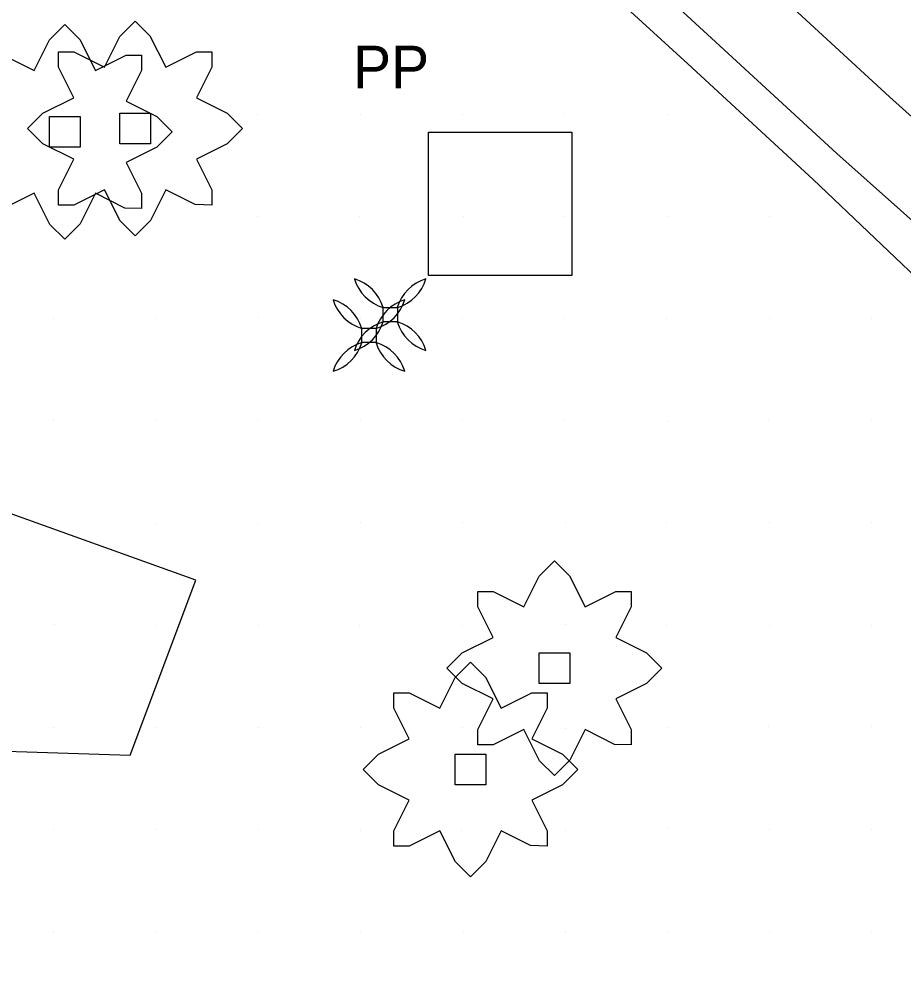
# Model space of a CAD drawing. Extents: x 1602514 to 1609837, y 863887 to 871157.
# Drawn here: x 1605113.6 to 1605243.4, y 866343.2 to 866482.9 of the extents above; entities that cross this region are included whole.
import ezdxf

# ---------------------------------------------------------------- set-up
doc = ezdxf.new("R2010")
doc.units = 0
for name, color, linetype in [('Environmental-New trees', 7, 'Continuous'), ('Photo-Anchor', 7, 'Continuous'), ('Survey-Centerline', 7, 'Continuous'), ('Survey-Edge of pavement', 7, 'Continuous'), ('Survey-Shoulders', 7, 'Continuous'), ('Survey-Spot dirt', 7, 'Continuous'), ('Survey-Vegetation trees', 7, 'Continuous'), ('Utility-Pole', 7, 'Continuous')]:
    doc.layers.add(name, color=color, linetype=linetype)

msp = doc.modelspace()

# ---------------------------------------------------------------- linework, layer by layer
at = {"layer": 'Environmental-New trees'}
msp.add_lwpolyline([(1605111.28, 866477.59), (1605115.78, 866475.34), (1605118.03, 866479.84), (1605120.28, 866482.1), (1605122.47, 866479.9), (1605124.78, 866475.34), (1605129.28, 866477.59), (1605131.53, 866477.59), (1605131.53, 866475.34), (1605129.28, 866470.84), (1605133.78, 866468.59), (1605136.03, 866466.34), (1605133.78, 866464.09), (1605129.28, 866461.84), (1605131.53, 866457.34), (1605131.53, 866455.09), (1605129.11, 866455.17), (1605124.78, 866457.34), (1605122.53, 866452.84), (1605120.28, 866450.59), (1605118.09, 866452.78), (1605115.78, 866457.34), (1605111.28, 866455.09)], dxfattribs=at)
msp.add_lwpolyline([(1605111.28, 866477.59), (1605115.78, 866475.34), (1605118.03, 866479.84), (1605120.28, 866482.1), (1605122.47, 866479.9), (1605124.78, 866475.34), (1605129.28, 866477.59), (1605131.53, 866477.59), (1605131.53, 866475.34), (1605129.28, 866470.84), (1605133.78, 866468.59), (1605136.03, 866466.34), (1605133.78, 866464.09), (1605129.28, 866461.84), (1605131.53, 866457.34), (1605131.53, 866455.09), (1605129.11, 866455.17), (1605124.78, 866457.34), (1605122.53, 866452.84), (1605120.28, 866450.59), (1605118.09, 866452.78), (1605115.78, 866457.34), (1605111.28, 866455.09)], dxfattribs=at)
for points in [[(1605119.34, 866478.12), (1605121.59, 866478.12), (1605126.09, 866475.87), (1605128.34, 866480.37), (1605130.59, 866482.62), (1605132.78, 866480.43), (1605135.09, 866475.87), (1605139.59, 866478.12), (1605141.84, 866478.12), (1605141.84, 866475.87), (1605139.59, 866471.37), (1605144.09, 866469.12), (1605146.34, 866466.87), (1605144.09, 866464.62), (1605139.59, 866462.37), (1605141.84, 866457.87), (1605141.84, 866455.62), (1605139.41, 866455.7), (1605135.09, 866457.87), (1605132.84, 866453.37), (1605130.59, 866451.12), (1605128.4, 866453.31), (1605126.09, 866457.87), (1605121.59, 866455.62), (1605119.34, 866455.62), (1605119.34, 866457.87), (1605121.59, 866462.37), (1605117.08, 866464.62), (1605114.83, 866466.87), (1605117.08, 866469.12), (1605121.59, 866471.37), (1605119.34, 866475.87)], [(1605119.34, 866478.12), (1605121.59, 866478.12), (1605126.09, 866475.87), (1605128.34, 866480.37), (1605130.59, 866482.62), (1605132.78, 866480.43), (1605135.09, 866475.87), (1605139.59, 866478.12), (1605141.84, 866478.12), (1605141.84, 866475.87), (1605139.59, 866471.37), (1605144.09, 866469.12), (1605146.34, 866466.87), (1605144.09, 866464.62), (1605139.59, 866462.37), (1605141.84, 866457.87), (1605141.84, 866455.62), (1605139.41, 866455.7), (1605135.09, 866457.87), (1605132.84, 866453.37), (1605130.59, 866451.12), (1605128.4, 866453.31), (1605126.09, 866457.87), (1605121.59, 866455.62), (1605119.34, 866455.62), (1605119.34, 866457.87), (1605121.59, 866462.37), (1605117.08, 866464.62), (1605114.83, 866466.87), (1605117.08, 866469.12), (1605121.59, 866471.37), (1605119.34, 866475.87)], [(1605122.53, 866468.59), (1605122.53, 866464.09), (1605118.03, 866464.09), (1605118.03, 866468.59)], [(1605122.53, 866468.59), (1605122.53, 866464.09), (1605118.03, 866464.09), (1605118.03, 866468.59)], [(1605132.84, 866469.12), (1605132.84, 866464.62), (1605128.34, 866464.62), (1605128.34, 866469.12)], [(1605132.84, 866469.12), (1605132.84, 866464.62), (1605128.34, 866464.62), (1605128.34, 866469.12)], [(1605180.84, 866398.9), (1605183.09, 866398.9), (1605187.59, 866396.65), (1605189.84, 866401.15), (1605192.09, 866403.4), (1605194.29, 866401.21), (1605196.59, 866396.65), (1605201.09, 866398.9), (1605203.34, 866398.9), (1605203.34, 866396.65), (1605201.09, 866392.15), (1605205.6, 866389.9), (1605207.85, 866387.65), (1605205.6, 866385.4), (1605201.09, 866383.15), (1605203.34, 866378.65), (1605203.34, 866376.4), (1605200.92, 866376.48), (1605196.59, 866378.65), (1605194.34, 866374.15), (1605192.09, 866371.9), (1605189.9, 866374.09), (1605187.59, 866378.65), (1605183.09, 866376.4), (1605180.84, 866376.4), (1605180.84, 866378.65), (1605183.09, 866383.15), (1605178.59, 866385.4), (1605176.34, 866387.65), (1605178.59, 866389.9), (1605183.09, 866392.15), (1605180.84, 866396.65)], [(1605180.84, 866398.9), (1605183.09, 866398.9), (1605187.59, 866396.65), (1605189.84, 866401.15), (1605192.09, 866403.4), (1605194.29, 866401.21), (1605196.59, 866396.65), (1605201.09, 866398.9), (1605203.34, 866398.9), (1605203.34, 866396.65), (1605201.09, 866392.15), (1605205.6, 866389.9), (1605207.85, 866387.65), (1605205.6, 866385.4), (1605201.09, 866383.15), (1605203.34, 866378.65), (1605203.34, 866376.4), (1605200.92, 866376.48), (1605196.59, 866378.65), (1605194.34, 866374.15), (1605192.09, 866371.9), (1605189.9, 866374.09), (1605187.59, 866378.65), (1605183.09, 866376.4), (1605180.84, 866376.4), (1605180.84, 866378.65), (1605183.09, 866383.15), (1605178.59, 866385.4), (1605176.34, 866387.65), (1605178.59, 866389.9), (1605183.09, 866392.15), (1605180.84, 866396.65)], [(1605194.34, 866389.9), (1605194.34, 866385.4), (1605189.84, 866385.4), (1605189.84, 866389.9)], [(1605194.34, 866389.9), (1605194.34, 866385.4), (1605189.84, 866385.4), (1605189.84, 866389.9)], [(1605168.53, 866384.06), (1605170.78, 866384.06), (1605175.28, 866381.81), (1605177.53, 866386.31), (1605179.78, 866388.56), (1605181.97, 866386.37), (1605184.28, 866381.81), (1605188.78, 866384.06), (1605191.03, 866384.06), (1605191.03, 866381.81), (1605188.78, 866377.31), (1605193.28, 866375.06), (1605195.53, 866372.81), (1605193.28, 866370.56), (1605188.78, 866368.31), (1605191.03, 866363.81), (1605191.03, 866361.56), (1605188.61, 866361.64), (1605184.28, 866363.81), (1605182.03, 866359.31), (1605179.78, 866357.06), (1605177.59, 866359.25), (1605175.28, 866363.81), (1605170.78, 866361.56), (1605168.53, 866361.56), (1605168.53, 866363.81), (1605170.78, 866368.31), (1605166.28, 866370.56), (1605164.03, 866372.81), (1605166.28, 866375.06), (1605170.78, 866377.31), (1605168.53, 866381.81)], [(1605168.53, 866384.06), (1605170.78, 866384.06), (1605175.28, 866381.81), (1605177.53, 866386.31), (1605179.78, 866388.56), (1605181.97, 866386.37), (1605184.28, 866381.81), (1605188.78, 866384.06), (1605191.03, 866384.06), (1605191.03, 866381.81), (1605188.78, 866377.31), (1605193.28, 866375.06), (1605195.53, 866372.81), (1605193.28, 866370.56), (1605188.78, 866368.31), (1605191.03, 866363.81), (1605191.03, 866361.56), (1605188.61, 866361.64), (1605184.28, 866363.81), (1605182.03, 866359.31), (1605179.78, 866357.06), (1605177.59, 866359.25), (1605175.28, 866363.81), (1605170.78, 866361.56), (1605168.53, 866361.56), (1605168.53, 866363.81), (1605170.78, 866368.31), (1605166.28, 866370.56), (1605164.03, 866372.81), (1605166.28, 866375.06), (1605170.78, 866377.31), (1605168.53, 866381.81)], [(1605182.03, 866375.06), (1605182.03, 866370.56), (1605177.53, 866370.56), (1605177.53, 866375.06)], [(1605182.03, 866375.06), (1605182.03, 866370.56), (1605177.53, 866370.56), (1605177.53, 866375.06)]]:
    msp.add_lwpolyline(points, close=True, dxfattribs=at)
at = {"layer": 'Photo-Anchor'}
for points in [[(1605166.96, 866440.58), (1605169.06, 866440.58), (1605169.06, 866438.48), (1605166.96, 866438.48)], [(1605166.96, 866440.58), (1605169.06, 866440.58), (1605169.06, 866438.48), (1605166.96, 866438.48)], [(1605163.85, 866437.53), (1605165.95, 866437.53), (1605165.95, 866435.43), (1605163.85, 866435.43)], [(1605163.85, 866437.53), (1605165.95, 866437.53), (1605165.95, 866435.43), (1605163.85, 866435.43)]]:
    msp.add_lwpolyline(points, close=True, dxfattribs=at)
for centre, radius, start, end in [((1605160.96, 866438.78), 6.27, 16.7236, 73.2821), ((1605168.78, 866446.6), 6.29, 196.8106, 253.1951), ((1605160.96, 866438.78), 6.27, 16.7236, 73.2821), ((1605168.78, 866446.6), 6.29, 196.8106, 253.1951), ((1605175.06, 866438.78), 6.27, 106.7179, 163.2764), ((1605167.24, 866446.6), 6.29, 286.8049, 343.1894), ((1605175.06, 866438.78), 6.27, 106.7179, 163.2764), ((1605167.24, 866446.6), 6.29, 286.8049, 343.1894), ((1605157.84, 866435.72), 6.27, 16.7236, 73.2821), ((1605165.66, 866443.54), 6.29, 196.8106, 253.1951), ((1605157.84, 866435.72), 6.27, 16.7236, 73.2821), ((1605165.66, 866443.54), 6.29, 196.8106, 253.1951), ((1605171.95, 866435.72), 6.27, 106.7179, 163.2764), ((1605164.13, 866443.54), 6.29, 286.8049, 343.1894), ((1605171.95, 866435.72), 6.27, 106.7179, 163.2764), ((1605164.13, 866443.54), 6.29, 286.8049, 343.1894), ((1605160.96, 866440.29), 6.27, 286.7179, 343.2764), ((1605168.78, 866432.46), 6.29, 106.8049, 163.1894), ((1605160.96, 866440.29), 6.27, 286.7179, 343.2764), ((1605168.78, 866432.46), 6.29, 106.8049, 163.1894), ((1605175.06, 866440.29), 6.27, 196.7236, 253.2821), ((1605167.24, 866432.46), 6.29, 16.8106, 73.1951), ((1605175.06, 866440.29), 6.27, 196.7236, 253.2821), ((1605167.24, 866432.46), 6.29, 16.8106, 73.1951), ((1605157.84, 866437.23), 6.27, 286.7179, 343.2764), ((1605165.66, 866429.41), 6.29, 106.8049, 163.1894), ((1605157.84, 866437.23), 6.27, 286.7179, 343.2764), ((1605165.66, 866429.41), 6.29, 106.8049, 163.1894), ((1605171.95, 866437.23), 6.27, 196.7236, 253.2821), ((1605164.13, 866429.41), 6.29, 16.8106, 73.1951), ((1605171.95, 866437.23), 6.27, 196.7236, 253.2821), ((1605164.13, 866429.41), 6.29, 16.8106, 73.1951)]:
    msp.add_arc(centre, radius, start, end, dxfattribs=at)
at = {"layer": 'Survey-Centerline'}
msp.add_lwpolyline([(1605037.69, 866656.39), (1605055.94, 866639.3), (1605074.48, 866622.54), (1605093.22, 866605.99), (1605111.81, 866589.27), (1605130.38, 866572.54), (1605149.03, 866555.9), (1605167.54, 866539.1), (1605186.09, 866522.35), (1605204.45, 866505.38), (1605222.87, 866488.48), (1605241.24, 866471.52), (1605259.83, 866454.8), (1605278.24, 866437.88), (1605296.47, 866420.77), (1605314.1, 866402.9), (1605330.94, 866384.38), (1605346.83, 866365.09), (1605361.55, 866344.83), (1605375.5, 866323.96)], dxfattribs=at)
msp.add_lwpolyline([(1605037.69, 866656.39), (1605055.94, 866639.3), (1605074.48, 866622.54), (1605093.22, 866605.99), (1605111.81, 866589.27), (1605130.38, 866572.54), (1605149.03, 866555.9), (1605167.54, 866539.1), (1605186.09, 866522.35), (1605204.45, 866505.38), (1605222.87, 866488.48), (1605241.24, 866471.52), (1605259.83, 866454.8), (1605278.24, 866437.88), (1605296.47, 866420.77), (1605314.1, 866402.9), (1605330.94, 866384.38), (1605346.83, 866365.09), (1605361.55, 866344.83), (1605375.5, 866323.96)], dxfattribs=at)
at = {"layer": 'Survey-Edge of pavement'}
msp.add_lwpolyline([(1605024.15, 866652.85), (1605048.37, 866630.9), (1605067.06, 866614.3), (1605085.84, 866597.8), (1605104.37, 866581.02), (1605122.94, 866564.29), (1605141.59, 866547.64), (1605160.11, 866530.85), (1605178.38, 866513.98), (1605196.73, 866497.01), (1605215.15, 866480.11), (1605233.53, 866463.16), (1605252.21, 866446.54), (1605270.61, 866429.62), (1605288.84, 866412.51), (1605305.39, 866395.8), (1605322.22, 866377.27), (1605338.18, 866358.03), (1605352.89, 866337.77)], dxfattribs=at)
msp.add_lwpolyline([(1605024.15, 866652.85), (1605048.37, 866630.9), (1605067.06, 866614.3), (1605085.84, 866597.8), (1605104.37, 866581.02), (1605122.94, 866564.29), (1605141.59, 866547.64), (1605160.11, 866530.85), (1605178.38, 866513.98), (1605196.73, 866497.01), (1605215.15, 866480.11), (1605233.53, 866463.16), (1605252.21, 866446.54), (1605270.61, 866429.62), (1605288.84, 866412.51), (1605305.39, 866395.8), (1605322.22, 866377.27), (1605338.18, 866358.03), (1605352.89, 866337.77)], dxfattribs=at)
at = {"layer": 'Survey-Shoulders'}
msp.add_lwpolyline([(1605020.8, 866649.24), (1605044.41, 866626.5), (1605062.62, 866609.38), (1605081.95, 866593.48), (1605100.89, 866577.16), (1605119.46, 866560.43), (1605138.12, 866543.79), (1605156.63, 866526.99), (1605174.63, 866509.92), (1605193.24, 866493.23), (1605211.66, 866476.33), (1605230.03, 866459.38), (1605248.15, 866442.14), (1605266.22, 866424.86), (1605284.45, 866407.75), (1605300.72, 866391.99), (1605317.55, 866373.46), (1605333.45, 866354.17), (1605347.38, 866333.28)], dxfattribs=at)
msp.add_lwpolyline([(1605020.8, 866649.24), (1605044.41, 866626.5), (1605062.62, 866609.38), (1605081.95, 866593.48), (1605100.89, 866577.16), (1605119.46, 866560.43), (1605138.12, 866543.79), (1605156.63, 866526.99), (1605174.63, 866509.92), (1605193.24, 866493.23), (1605211.66, 866476.33), (1605230.03, 866459.38), (1605248.15, 866442.14), (1605266.22, 866424.86), (1605284.45, 866407.75), (1605300.72, 866391.99), (1605317.55, 866373.46), (1605333.45, 866354.17), (1605347.38, 866333.28)], dxfattribs=at)
at = {"layer": 'Survey-Spot dirt'}
for p, q in [((1605133.85, 866468.98), (1605133.85, 866468.98)), ((1605133.85, 866468.98), (1605133.85, 866468.98)), ((1605148.55, 866468.93), (1605148.55, 866468.93)), ((1605148.55, 866468.93), (1605148.55, 866468.93)), ((1605163.62, 866468.96), (1605163.62, 866468.96)), ((1605163.62, 866468.96), (1605163.62, 866468.96)), ((1605178.64, 866468.96), (1605178.64, 866468.96)), ((1605178.64, 866468.96), (1605178.64, 866468.96)), ((1605193.63, 866469), (1605193.63, 866469)), ((1605193.63, 866469), (1605193.63, 866469)), ((1605208.61, 866468.97), (1605208.61, 866468.97)), ((1605208.61, 866468.97), (1605208.61, 866468.97)), ((1605118.65, 866453.88), (1605118.65, 866453.88)), ((1605118.65, 866453.88), (1605118.65, 866453.88)), ((1605133.62, 866453.92), (1605133.62, 866453.92)), ((1605133.62, 866453.92), (1605133.62, 866453.92)), ((1605148.62, 866453.88), (1605148.62, 866453.88)), ((1605148.62, 866453.88), (1605148.62, 866453.88)), ((1605163.5, 866453.99), (1605163.5, 866453.99)), ((1605163.5, 866453.99), (1605163.5, 866453.99)), ((1605178.71, 866453.96), (1605178.71, 866453.96)), ((1605178.71, 866453.96), (1605178.71, 866453.96)), ((1605193.6, 866453.96), (1605193.6, 866453.96)), ((1605193.6, 866453.96), (1605193.6, 866453.96)), ((1605208.66, 866453.93), (1605208.66, 866453.93)), ((1605208.66, 866453.93), (1605208.66, 866453.93)), ((1605223.61, 866453.99), (1605223.61, 866453.99)), ((1605223.61, 866453.99), (1605223.61, 866453.99)), ((1605118.68, 866438.93), (1605118.68, 866438.93)), ((1605118.68, 866438.93), (1605118.68, 866438.93)), ((1605133.57, 866438.97), (1605133.57, 866438.97)), ((1605133.57, 866438.97), (1605133.57, 866438.97)), ((1605148.66, 866439.11), (1605148.66, 866439.11)), ((1605148.66, 866439.11), (1605148.66, 866439.11)), ((1605163.69, 866439), (1605163.69, 866439)), ((1605163.69, 866439), (1605163.69, 866439)), ((1605178.56, 866439.02), (1605178.56, 866439.02)), ((1605178.56, 866439.02), (1605178.56, 866439.02)), ((1605193.62, 866438.98), (1605193.62, 866438.98)), ((1605193.62, 866438.98), (1605193.62, 866438.98)), ((1605208.59, 866439.04), (1605208.59, 866439.04)), ((1605208.59, 866439.04), (1605208.59, 866439.04)), ((1605223.65, 866438.97), (1605223.65, 866438.97)), ((1605223.65, 866438.97), (1605223.65, 866438.97)), ((1605238.65, 866438.99), (1605238.65, 866438.99)), ((1605238.65, 866438.99), (1605238.65, 866438.99)), ((1605118.58, 866423.95), (1605118.58, 866423.95)), ((1605118.58, 866423.95), (1605118.58, 866423.95)), ((1605133.64, 866424), (1605133.64, 866424)), ((1605133.64, 866424), (1605133.64, 866424)), ((1605148.61, 866424.04), (1605148.61, 866424.04)), ((1605148.61, 866424.04), (1605148.61, 866424.04)), ((1605163.65, 866423.96), (1605163.65, 866423.96)), ((1605163.65, 866423.96), (1605163.65, 866423.96)), ((1605178.67, 866423.95), (1605178.67, 866423.95)), ((1605178.67, 866423.95), (1605178.67, 866423.95)), ((1605193.56, 866424.1), (1605193.56, 866424.1)), ((1605193.56, 866424.1), (1605193.56, 866424.1)), ((1605208.68, 866423.92), (1605208.68, 866423.92)), ((1605208.68, 866423.92), (1605208.68, 866423.92)), ((1605223.56, 866424.01), (1605223.56, 866424.01)), ((1605223.56, 866424.01), (1605223.56, 866424.01)), ((1605238.64, 866423.94), (1605238.64, 866423.94)), ((1605238.64, 866423.94), (1605238.64, 866423.94)), ((1605118.68, 866409.03), (1605118.68, 866409.03)), ((1605118.68, 866409.03), (1605118.68, 866409.03)), ((1605133.59, 866408.93), (1605133.59, 866408.93)), ((1605133.59, 866408.93), (1605133.59, 866408.93)), ((1605148.61, 866408.95), (1605148.61, 866408.95)), ((1605148.61, 866408.95), (1605148.61, 866408.95)), ((1605163.65, 866408.97), (1605163.65, 866408.97)), ((1605163.65, 866408.97), (1605163.65, 866408.97)), ((1605178.66, 866409), (1605178.66, 866409)), ((1605178.66, 866409), (1605178.66, 866409)), ((1605193.71, 866408.98), (1605193.71, 866408.98)), ((1605193.71, 866408.98), (1605193.71, 866408.98)), ((1605208.56, 866408.99), (1605208.56, 866408.99)), ((1605208.56, 866408.99), (1605208.56, 866408.99)), ((1605223.62, 866408.99), (1605223.62, 866408.99)), ((1605223.62, 866408.99), (1605223.62, 866408.99)), ((1605238.62, 866408.98), (1605238.62, 866408.98)), ((1605238.62, 866408.98), (1605238.62, 866408.98)), ((1605118.73, 866394.07), (1605118.73, 866394.07)), ((1605118.73, 866394.07), (1605118.73, 866394.07)), ((1605133.6, 866393.97), (1605133.6, 866393.97)), ((1605133.6, 866393.97), (1605133.6, 866393.97)), ((1605148.67, 866393.98), (1605148.67, 866393.98)), ((1605148.67, 866393.98), (1605148.67, 866393.98)), ((1605163.55, 866393.88), (1605163.55, 866393.88)), ((1605163.55, 866393.88), (1605163.55, 866393.88)), ((1605178.62, 866394), (1605178.62, 866394)), ((1605178.62, 866394), (1605178.62, 866394)), ((1605193.68, 866394.07), (1605193.68, 866394.07)), ((1605193.68, 866394.07), (1605193.68, 866394.07)), ((1605208.57, 866393.96), (1605208.57, 866393.96)), ((1605208.57, 866393.96), (1605208.57, 866393.96)), ((1605223.69, 866394), (1605223.69, 866394)), ((1605223.69, 866394), (1605223.69, 866394)), ((1605238.59, 866393.93), (1605238.59, 866393.93)), ((1605238.59, 866393.93), (1605238.59, 866393.93)), ((1605118.59, 866379), (1605118.59, 866379)), ((1605118.59, 866379), (1605118.59, 866379)), ((1605133.62, 866378.91), (1605133.62, 866378.91)), ((1605133.62, 866378.91), (1605133.62, 866378.91)), ((1605148.67, 866378.97), (1605148.67, 866378.97)), ((1605148.67, 866378.97), (1605148.67, 866378.97)), ((1605163.61, 866379.03), (1605163.61, 866379.03)), ((1605163.61, 866379.03), (1605163.61, 866379.03)), ((1605178.68, 866378.93), (1605178.68, 866378.93)), ((1605178.68, 866378.93), (1605178.68, 866378.93)), ((1605193.73, 866378.81), (1605193.73, 866378.81)), ((1605193.73, 866378.81), (1605193.73, 866378.81)), ((1605208.61, 866378.96), (1605208.61, 866378.96)), ((1605208.61, 866378.96), (1605208.61, 866378.96)), ((1605223.54, 866379.04), (1605223.54, 866379.04)), ((1605223.54, 866379.04), (1605223.54, 866379.04)), ((1605238.65, 866379.04), (1605238.65, 866379.04)), ((1605238.65, 866379.04), (1605238.65, 866379.04)), ((1605118.6, 866363.97), (1605118.6, 866363.97)), ((1605118.6, 866363.97), (1605118.6, 866363.97)), ((1605133.59, 866363.95), (1605133.59, 866363.95)), ((1605133.59, 866363.95), (1605133.59, 866363.95)), ((1605148.67, 866364.02), (1605148.67, 866364.02)), ((1605148.67, 866364.02), (1605148.67, 866364.02)), ((1605163.65, 866363.81), (1605163.65, 866363.81)), ((1605163.65, 866363.81), (1605163.65, 866363.81)), ((1605178.48, 866363.85), (1605178.48, 866363.85)), ((1605178.48, 866363.85), (1605178.48, 866363.85)), ((1605193.65, 866363.88), (1605193.65, 866363.88)), ((1605193.65, 866363.88), (1605193.65, 866363.88)), ((1605208.68, 866364.08), (1605208.68, 866364.08)), ((1605208.68, 866364.08), (1605208.68, 866364.08)), ((1605223.62, 866363.96), (1605223.62, 866363.96)), ((1605223.62, 866363.96), (1605223.62, 866363.96)), ((1605238.61, 866363.96), (1605238.61, 866363.96)), ((1605238.61, 866363.96), (1605238.61, 866363.96)), ((1605133.68, 866349.02), (1605133.68, 866349.02)), ((1605133.68, 866349.02), (1605133.68, 866349.02)), ((1605178.7, 866349.04), (1605178.7, 866349.04)), ((1605178.7, 866349.04), (1605178.7, 866349.04)), ((1605208.62, 866349.02), (1605208.62, 866349.02)), ((1605208.62, 866349.02), (1605208.62, 866349.02)), ((1605118.61, 866348.99), (1605118.61, 866348.99)), ((1605118.61, 866348.99), (1605118.61, 866348.99)), ((1605148.6, 866348.95), (1605148.6, 866348.95)), ((1605148.6, 866348.95), (1605148.6, 866348.95)), ((1605163.61, 866348.94), (1605163.61, 866348.94)), ((1605163.61, 866348.94), (1605163.61, 866348.94)), ((1605193.73, 866349), (1605193.73, 866349)), ((1605193.73, 866349), (1605193.73, 866349)), ((1605223.59, 866348.98), (1605223.59, 866348.98)), ((1605223.59, 866348.98), (1605223.59, 866348.98)), ((1605238.64, 866348.95), (1605238.64, 866348.95)), ((1605238.64, 866348.95), (1605238.64, 866348.95))]:
    msp.add_line(p, q, dxfattribs=at)
at = {"layer": 'Survey-Vegetation trees'}
msp.add_lwpolyline([(1604912.54, 866195.31), (1604962.16, 866214.64), (1605008.12, 866242.86), (1605048.31, 866263.06), (1605081.2, 866309.61), (1605090.56, 866347.87), (1605096.44, 866375.96), (1605129.87, 866374.89), (1605139.49, 866400.58), (1605105.26, 866412.88), (1605083.87, 866433.22), (1605033.87, 866450.34), (1605027.45, 866418.77), (1605050.18, 866406.2), (1605000.45, 866346.8), (1604986.81, 866313.09), (1604949.64, 866288.21), (1604912.47, 866279.64), (1604880.92, 866247.27)], dxfattribs=at)
msp.add_lwpolyline([(1604912.54, 866195.31), (1604962.16, 866214.64), (1605008.12, 866242.86), (1605048.31, 866263.06), (1605081.2, 866309.61), (1605090.56, 866347.87), (1605096.44, 866375.96), (1605129.87, 866374.89), (1605139.49, 866400.58), (1605105.26, 866412.88), (1605083.87, 866433.22), (1605033.87, 866450.34), (1605027.45, 866418.77), (1605050.18, 866406.2), (1605000.45, 866346.8), (1604986.81, 866313.09), (1604949.64, 866288.21), (1604912.47, 866279.64), (1604880.92, 866247.27)], dxfattribs=at)
at = {"layer": 'Utility-Pole'}
msp.add_lwpolyline([(1605173.63, 866466.29), (1605194.64, 866466.29), (1605194.64, 866445.28), (1605173.63, 866445.28)], close=True, dxfattribs=at)
msp.add_lwpolyline([(1605173.63, 866466.29), (1605194.64, 866466.29), (1605194.64, 866445.28), (1605173.63, 866445.28)], close=True, dxfattribs=at)

# ---------------------------------------------------------------- texts
msp.add_text('PP', height=6.251, dxfattribs=at).set_placement((1605162.57, 866472.75))
msp.add_text('PP', height=6.251, dxfattribs=at).set_placement((1605162.57, 866472.75))

doc.saveas('drawing.dxf')
